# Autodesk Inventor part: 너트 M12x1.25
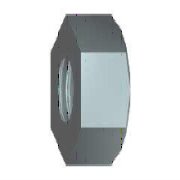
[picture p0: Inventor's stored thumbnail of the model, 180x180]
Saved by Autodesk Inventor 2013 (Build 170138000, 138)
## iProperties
IsCustomPart: 0
Created: 2015-12
Part Number: 너트 M12x1.25
Material: 스테인리스강
Description: 6각 너트
Document SubType Name: Modeling
Standard: KS B 1012
Designer: mdu
Standards Organization: KS
Language: ko-KR
Size Designation: M12x1.25
Categories: <MemberInstance><Categories><Category DisplayName="조임쇠" InternalName="e4da775c-781d-43d5-af7c-5136215cf5a6" Mnemonic="FSTN"><Category DisplayName="너트" InternalN
Density: 8.08 g/cm^3
Mass: 17.9325 g
Surface Area: 14.0653 cm^2
Volume: 2.21937 cm^3
Author: mdu
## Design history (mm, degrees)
sketch "스케치1"
  geometry: L1 (10.97, 0)-(5.485, -9.5); L2 (5.485, -9.5)-(-5.485, -9.5); L3 (-5.485, -9.5)-(-10.97, 0); L4 (-10.97, 0)-(-5.485, 9.5); L5 (-5.485, 9.5)-(5.485, 9.5); L6 (5.485, 9.5)-(10.97, 0); 2 further points
  constraints: 12 end point, 1 coincident, 1 horizontal, 11 other
  dimensions: "d0" = 21.93931 distance of L1.start L3.end (= 1.1547 x SW)
extrude "본체" new body sketch "스케치1" distance "d1" = 10 (= KOH); taper "d2" = 0 deg
sketch "스케치2"
  geometry: 1 further point
hole "스레드" sketch "스케치2" diameter "d6" = 10.647; stored, may be unused: countersink angle "d10" = 82 deg, drill point angle "d12" = 118 deg; dims "d7" = 12.7, "d8" = 9.525, "d9" = 6.35, "d11" = 19.05
sketch "스케치3"
  geometry: L1 (0, 10.97)-(10, 10.97) reference; L2 (10, 5.485)-(10, 10.97) reference; L3 (-2, 0)-(12, 0) reference; L4 (9.151, 10.97)-(10, 9.5)
  constraints: 2 end point, 2 point on line
  dimensions: "d3" = 19 diameter of L4.end L3 (= SW01); "d4" = 30 deg angle of L2 L4 (= ANG2)
revolve "모따기3" sketch "스케치3" stored, may be unused: angle "d5" = 90 deg
workaxis "Work Axis1"
workplane "Work Plane1"
body "Solid1"
chamfer "모따기1" distance "d13" = 0.67658 (= -0.5 x GD1 + 0.5 x NND); stored, may be unused: angle "d14" = 30 deg, second distance "d21" = 0.67658 (= -0.5 x GD1 + 0.5 x NND)
chamfer "모따기2" distance "d15" = 0.67658 (= -0.5 x GD1 + 0.5 x NND); stored, may be unused: angle "d16" = 30 deg, second distance "d22" = 0.67658 (= -0.5 x GD1 + 0.5 x NND)
other parameters: "ANG2" = 30 deg [user parameter; used in 1 equation term], "NND" = 12 [user parameter; used in 4 equation terms], "KOH" = 10 [user parameter; used in 1 equation term], "SW" = 19 [user parameter; used in 3 equation terms], "SW01" = 19 (= SW) [user parameter; used in 1 equation term], "GD1" = 10.64684 (computed from THREADDIA, PTC, TOA) [user parameter; used in 4 equation terms], "d19" = 0, "d20" = 0, "d24" = 0, "d25" = 0, "GUL" = 0.67658 (= 0.541266 x PTC) [user parameter], "TPU" = 8 (computed from PTC) [user parameter], "TOA" = 30 deg [user parameter; used in 1 equation term], "PTC" = 1.25 [user parameter; used in 4 equation terms], "E0" = 21.945 (= 1.155 x SW) [user parameter], "THREADDIA" = 12 [user parameter; used in 1 equation term], "GAL" = 0.67658 (= 0.541266 x PTC) [user parameter]
